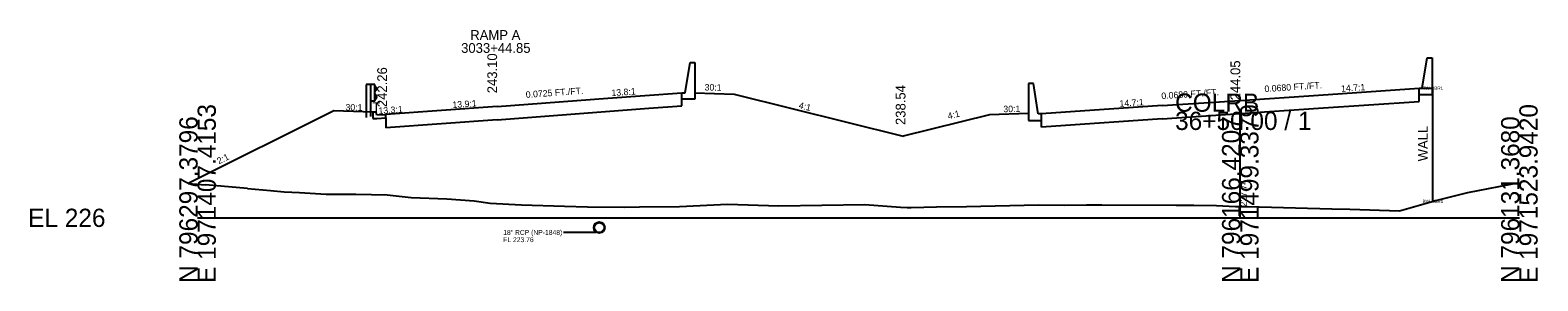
# Model space of a CAD drawing. Extents: x -26 to 1971766, y -10 to 796432.
# Drawn here: x -25.7 to 205.7, y 990.3 to 1028.8 of the extents above; entities that cross this region are included whole.
import ezdxf

# ---------------------------------------------------------------- set-up
doc = ezdxf.new("R2010")
doc.units = 0
for name, color, linetype in [('BR_AUTO DIMENSION', 7, 'Continuous'), ('BR_BORDER LINES', 7, 'Continuous'), ('BR_CENTER LINES', 7, 'Continuous'), ('BR_CONCRETE', 7, 'Continuous'), ('BR_PRESTRESSED BEAM', 7, 'Continuous'), ('BR_REBAR', 7, 'Continuous'), ('BR_STRUCTURAL STEEL', 7, 'Continuous'), ('Default', 7, 'Continuous'), ('North Arrow', 7, 'Continuous'), ('RD_DDB_Profile_Lbl', 7, 'Continuous'), ('RD_EX_Conc', 7, 'Continuous'), ('RD_EX_Road', 7, 'Continuous'), ('RD_HC_CL', 7, 'Continuous'), ('RD_HC_CL_Rel', 7, 'Continuous'), ('RD_PD_ALT1_TrvlWay', 7, 'Continuous'), ('RD_PD_ALT2_TnTmp', 7, 'Continuous'), ('RD_PD_Final_LnLine', 7, 'Continuous'), ('RD_PD_FOC', 7, 'Continuous'), ('RD_PD_GR', 7, 'Continuous'), ('RD_PD_MedBWall', 7, 'Continuous'), ('RD_PD_PaveShd', 7, 'Continuous'), ('RD_PD_WallFill', 7, 'Continuous'), ('RD_SHT_IplotShp', 7, 'Continuous')]:
    doc.layers.add(name, color=color, linetype=linetype)

msp = doc.modelspace()

# ---------------------------------------------------------------- linework, layer by layer
at = {"layer": 'BR_AUTO DIMENSION'}
for p, q in [((160, 1000), (160, 1016.3)), ((0, 1000), (160, 1000)), ((160, 1000), (202.83, 1000))]:
    msp.add_line(p, q, dxfattribs=at)
at = {"layer": 'BR_BORDER LINES'}
for p in [(-1.44, 1005.29), (7.65, 1004.49)]:
    msp.add_line(p, (1.2, 1005.06), dxfattribs=at)
msp.add_lwpolyline([(7.65, 1004.49), (11.2, 1004.18), (13.28, 1003.99), (15.64, 1003.9), (19.74, 1003.66), (24.26, 1003.62), (29.08, 1003.54), (32.77, 1003.13), (38.26, 1002.9), (42.45, 1002.62), (44.91, 1002.25), (49.71, 1002.02), (56.3, 1001.78), (59.84, 1001.69), (65.48, 1001.63), (67.8, 1001.7), (73.93, 1001.76), (81.3, 1002.11), (89.21, 1001.86), (102.41, 1002.06), (107.88, 1001.65), (108.89, 1001.57), (109.49, 1001.57), (113.4, 1001.67), (117.98, 1001.75), (129.03, 1001.97), (133.02, 1001.96), (136.41, 1002), (138.78, 1001.99), (150.16, 1001.96), (152.89, 1001.93), (156.37, 1001.91), (159.26, 1001.72), (160, 1001.74), (161.05, 1001.76), (174.07, 1001.36), (176.83, 1001.33), (184.45, 1001.09), (189.82, 1002.62), (194.92, 1003.87), (202.83, 1005.43)], dxfattribs=at)
at = {"layer": 'BR_CENTER LINES'}
msp.add_line((26.91, 1016.26), (20.91, 1016.46), dxfattribs=at)
at = {"layer": 'BR_PRESTRESSED BEAM'}
for p, q in [((26.91, 1016.26), (26.91, 1015.26)), ((26.91, 1016.26), (26.91, 1015.26)), ((26.91, 1015.26), (27.49, 1015.26)), ((27.49, 1015.26), (28.91, 1015.35))]:
    msp.add_line(p, q, dxfattribs=at)
at = {"layer": 'BR_STRUCTURAL STEEL'}
for p, q in [((187.43, 1019.92), (189.48, 1019.92)), ((189.48, 1019.92), (189.48, 1002.52))]:
    msp.add_line(p, q, dxfattribs=at)
at = {"layer": 'North Arrow'}
for p, q in [((45.96, 1017.1), (62.93, 1018.4)), ((148, 1017.24), (160, 1018.05)), ((160, 1018.05), (172, 1018.87))]:
    msp.add_line(p, q, dxfattribs=at)
at = {"layer": 'RD_EX_Conc'}
for p, q in [((27.41, 1016.26), (26.91, 1016.26)), ((27.41, 1016.26), (26.91, 1016.26)), ((27.49, 1015.76), (27.41, 1016.26)), ((27.49, 1015.76), (27.41, 1016.26)), ((28.91, 1015.85), (27.49, 1015.76)), ((28.91, 1015.87), (28.91, 1015.85)), ((129.5, 1015.98), (129.5, 1015.96))]:
    msp.add_line(p, q, dxfattribs=at)
at = {"layer": 'RD_EX_Road'}
for p, q in [((74.32, 1017.21), (74.32, 1019.22)), ((187.43, 1017.88), (187.43, 1019.92)), ((28.91, 1015.31), (28.91, 1015.87)), ((28.91, 1015.85), (28.91, 1015.87)), ((28.91, 1015.35), (28.91, 1015.85)), ((45.96, 1015.06), (69.27, 1016.84)), ((69.27, 1016.84), (74.32, 1017.21)), ((129.5, 1015.96), (129.5, 1015.98)), ((129.5, 1015.46), (129.5, 1015.96)), ((148, 1015.2), (160, 1016.01)), ((160, 1016.01), (172, 1016.83)), ((172, 1016.83), (187.43, 1017.88)), ((28.91, 1015.35), (28.91, 1013.83)), ((45.96, 1015.06), (28.91, 1013.83)), ((129.5, 1013.94), (129.5, 1015.46)), ((148, 1015.2), (129.5, 1013.94))]:
    msp.add_line(p, q, dxfattribs=at)
at = {"layer": 'RD_HC_CL'}
for p, q in [((26.55, 1020.49), (25.89, 1020.49)), ((25.89, 1020.49), (25.89, 1015.44)), ((27.22, 1020.49), (26.55, 1020.49)), ((26.55, 1020.49), (26.55, 1015.55)), ((27.22, 1017.92), (27.22, 1020.49)), ((27.22, 1020.33), (27.49, 1019.89)), ((27.49, 1019.78), (27.22, 1019.34)), ((27.49, 1018.63), (27.22, 1019.07)), ((27.22, 1018.08), (27.49, 1018.52)), ((27.49, 1019.89), (27.49, 1019.78)), ((27.49, 1018.52), (27.49, 1018.63)), ((27.22, 1017.92), (26.55, 1017.92))]:
    msp.add_line(p, q, dxfattribs=at)
at = {"layer": 'RD_PD_Final_LnLine'}
for p, q in [((76.32, 1019.22), (82.32, 1019.02)), ((82.32, 1019.02), (108.27, 1012.54)), ((20.91, 1016.46), (-1.44, 1005.29)), ((121.5, 1015.85), (108.27, 1012.54)), ((127.5, 1016.05), (121.5, 1015.85))]:
    msp.add_line(p, q, dxfattribs=at)
at = {"layer": 'RD_PD_FOC'}
msp.add_line((61.13, 997.76), (56.13, 997.76), dxfattribs=at)
for radius in [0.85, 0.75]:
    msp.add_circle((61.63, 998.51), radius, dxfattribs=at)
at = {"layer": 'RD_PD_GR'}
for p, q in [((74.82, 1019.22), (75.57, 1023.89)), ((75.57, 1023.89), (76.32, 1023.89)), ((76.32, 1023.89), (76.32, 1018.22)), ((187.93, 1019.92), (188.68, 1024.58)), ((188.68, 1024.58), (189.43, 1024.58)), ((189.43, 1024.58), (189.43, 1018.92)), ((128.25, 1020.64), (127.5, 1020.64)), ((127.5, 1020.64), (127.5, 1014.98)), ((129, 1015.98), (128.25, 1020.64)), ((74.32, 1018.22), (74.32, 1019.22)), ((74.32, 1019.22), (74.82, 1019.22)), ((76.32, 1018.22), (74.32, 1018.22)), ((187.43, 1018.92), (187.43, 1019.92)), ((187.43, 1019.92), (187.93, 1019.92)), ((189.43, 1018.92), (187.43, 1018.92)), ((129.5, 1015.98), (129, 1015.98)), ((129.5, 1014.98), (129.5, 1015.98)), ((127.5, 1014.98), (129.5, 1014.98))]:
    msp.add_line(p, q, dxfattribs=at)
at = {"layer": 'RD_PD_MedBWall'}
for p, q in [((62.93, 1018.4), (74.32, 1019.22)), ((172, 1018.87), (187.43, 1019.92)), ((45.96, 1017.1), (28.91, 1015.87)), ((148, 1017.24), (129.5, 1015.98))]:
    msp.add_line(p, q, dxfattribs=at)

# ---------------------------------------------------------------- texts
at = {"layer": 'BR_AUTO DIMENSION'}
for s, p in [('COLRB', (150, 1016.3)), ('36+50.00 / 1', (150, 1013.5)), ('EL 226', (-26, 998.6))]:
    msp.add_text(s, height=2.8, dxfattribs=at).set_placement(p)
for s, p in [('E 1971407.4153', (2.8, 990)), ('E 1971499.3379', (162.8, 990)), ('E 1971523.9420', (205.63, 990)), ('N 796297.3796', (0, 990)), ('N 796166.4207', (160, 990)), ('N 796131.3680', (202.83, 990))]:
    msp.add_text(s, height=2.8, rotation=90, dxfattribs=at).set_placement(p)
at = {"layer": 'BR_CONCRETE'}
for s, rotation, p in [('30:1', 359.1385, (77.8, 1019.57)), ('0.0680 FT./FT.', 3.8901, (163.75, 1019.31)), ('0.0725 FT./FT.', 4.1468, (50.4, 1018.42)), ('13.8:1', 4.1468, (63.55, 1018.69)), ('0.0680 FT./FT.', 3.8901, (147.93, 1018.23)), ('30:1', 359.1385, (22.69, 1016.5)), ('4:1', 345.9638, (92.18, 1016.85)), ('4:1', 14.0362, (115.24, 1015.13)), ('30:1', 0.8615, (123.65, 1016.22)), ('2:1', 26.5651, (3.28, 1008.21))]:
    msp.add_text(s, height=1, rotation=rotation, dxfattribs=at).set_placement(p)
at = {"layer": 'BR_REBAR'}
msp.add_text('LT', height=1.5, dxfattribs=at).set_placement((25.71, 1016.26))
at = {"layer": 'Default'}
for s, p in [('242.26', (29.07, 1017.01)), ('238.54', (108.63, 1014.26))]:
    msp.add_text(s, height=1.5, rotation=90, dxfattribs=at).set_placement(p)
at = {"layer": 'RD_DDB_Profile_Lbl'}
for s, p in [('TW RBR1', (188.02, 1019.67)), ('BW RBR1', (187.99, 1002.27))]:
    msp.add_text(s, height=0.5, dxfattribs=at).set_placement(p)
at = {"layer": 'RD_HC_CL_Rel'}
for s, p in [('243.10', (45.96, 1019.14)), ('244.05', (160, 1018.05))]:
    msp.add_text(s, height=1.5, rotation=90, dxfattribs=at).set_placement(p)
at = {"layer": 'RD_PD_ALT1_TrvlWay'}
for s, rotation, p in [('14.7:1', 3.8901, (175.5, 1019.36)), ('13.9:1', 4.1212, (39.14, 1016.86)), ('14.7:1', 3.8901, (141.5, 1017.05))]:
    msp.add_text(s, height=1, rotation=rotation, dxfattribs=at).set_placement(p)
at = {"layer": 'RD_PD_ALT2_TnTmp'}
msp.add_text('WALL', height=1.5, rotation=90, dxfattribs=at).set_placement((188.78, 1008.68))
at = {"layer": 'RD_PD_FOC'}
for s, p in [('18" RCP (NP-1848)', (46.9, 997.38)), ('FL 223.76', (46.9, 996.26))]:
    msp.add_text(s, height=0.75, dxfattribs=at).set_placement(p)
at = {"layer": 'RD_PD_PaveShd'}
msp.add_text('13.3:1', height=1, rotation=4.2992, dxfattribs=at).set_placement((27.8, 1015.93))
at = {"layer": 'RD_PD_WallFill'}
for s, p in [('RAMP A', (41.84, 1027.35)), ('3033+44.85', (40.44, 1025.35))]:
    msp.add_text(s, height=1.5, dxfattribs=at).set_placement(p)
at = {"layer": 'RD_SHT_IplotShp'}
msp.add_text('227.74', height=1, rotation=90, dxfattribs=at).set_placement((161, 1001.74))

doc.saveas('drawing.dxf')
